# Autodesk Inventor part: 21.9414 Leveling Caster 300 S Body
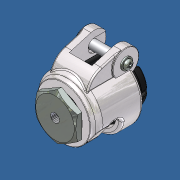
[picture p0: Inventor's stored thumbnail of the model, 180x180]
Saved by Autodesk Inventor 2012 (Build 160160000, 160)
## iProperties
Created: 2015-01
Part Number: 21.9414 Leveling Caster 300 S Body
Material: Default
Document SubType Name: Modeling
Designer: Admin
Density: 3.2276 g/cm^3
Mass: 589.67 g
Surface Area: 635.612 cm^2
Volume: 182.696 cm^3
Author: Admin
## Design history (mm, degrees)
feature "Base1"
body "Solid1"
